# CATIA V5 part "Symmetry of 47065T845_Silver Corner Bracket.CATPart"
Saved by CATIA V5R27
Part number: Symmetry of 47065T845_Silver Corner Bracket
Bounding box of the stored display mesh (mm): x 0 to 38.1, y -38.1 to 0, z -16.637 to 16.637
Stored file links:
  \\triton.meca.polymtl.ca\usagers\zaoue\profiles\Desktop\varm_ass\structure prismatique\Symmetry of 47065T845_Silver Corner Bracket.CATPart
  \\triton.meca.polymtl.ca\usagers\zaoue\profiles\Desktop\varm_ass\bearing assy\L_bracket_small.CATPart
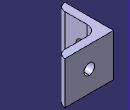
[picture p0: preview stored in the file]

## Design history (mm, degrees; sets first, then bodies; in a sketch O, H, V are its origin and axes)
Body1 (main body)
  Body2 "Corps du corps principal d'origine"
    Solid1: linked copy from another document
  Assemble1: tool Body2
